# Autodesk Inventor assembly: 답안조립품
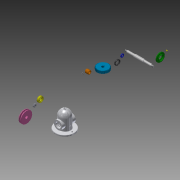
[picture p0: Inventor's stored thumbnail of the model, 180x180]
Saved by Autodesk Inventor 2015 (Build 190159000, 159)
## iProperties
Created: 2019-11
Part Number: 답안조립품
Document SubType Name: Assembly
Designer: now
Author: now
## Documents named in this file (14)
- C:\Users\now\Desktop\491104V1033\공용부품\답안조립품.iam
- C:\Users\now\Desktop\491104V1033\공용부품\V-벨트풀리.ipt
- V-벨트풀리.ipt
- C:\Users\now\Desktop\491104V1033\공용부품\너트 M12x1.25.ipt
- C:\Users\now\Desktop\491104V1033\공용부품\베어링 6203.ipt
- C:\Users\now\Desktop\491104V1033\공용부품\본체.ipt
- C:\Users\now\Desktop\491104V1033\공용부품\볼트 M4.ipt
- C:\Users\now\Desktop\491104V1033\공용부품\부시.ipt
- C:\Users\now\Desktop\491104V1033\공용부품\스퍼기어.ipt
- C:\Users\now\Desktop\491104V1033\공용부품\오일 실 26 38 8.ipt
- C:\Users\now\Desktop\491104V1033\공용부품\와셔 12x24.ipt
- C:\Users\now\Desktop\491104V1033\공용부품\축.ipt
- C:\Users\now\Desktop\491104V1033\공용부품\커버.ipt
- C:\Users\now\Desktop\491104V1033\공용부품\키 5x5x12.ipt
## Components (1 placed, 1 different names)
1. V-벨트풀리:1
